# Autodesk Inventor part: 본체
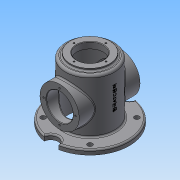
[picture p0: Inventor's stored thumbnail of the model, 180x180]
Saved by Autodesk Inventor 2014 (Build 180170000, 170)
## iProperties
Created: 2018-04
Part Number: 본체
Material: 일반
Document SubType Name: Modeling
Designer: NET
Density: 1 g/cm^3
Appearance: 기본값
Author: NET
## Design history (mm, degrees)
sketch "스케치1"
  geometry: L1 (0, 0)-(0, 133); L2 (0, 133)-(40, 133); L3 (40, 133)-(40, 128); L4 (40, 128)-(50, 128); L5 (50, 128)-(50, 0); L6 (50, 0)-(0, 0); L7 (27, 120)-(45, 120); L8 (45, 120)-(45, 0); L9 (0, 133)-(27, 133); L10 (27, 120)-(27, 133)
  constraints: 20 end point, 5 perpendicular, 2 parallel, 2 point on line, 1 vertical
  dimensions: "d0" = 133 distance of L1.start L1.end; "d1" = 80 diameter of L3 L1; "d2" = 100 diameter of L5 L1; "d4" = 5 distance of L2.end L3.end; "d12" = 90 diameter of L8 L1; "d14" = 13 distance of L7.start L9.end; "d15" = 54 diameter of L10 L1; "d16" = 120 distance of L7.end L8.end
revolve "회전1" stored, may be unused: angle "d5" = 90 deg
sketch "스케치2"
  geometry: L1 (-40, 133)-(40, 133) reference; L2 (-62, 68)-(62, 68); L3 (-50, 0)-(50, 0) reference; L4 (-62, 68)-(-62, 108); L5 (-62, 108)-(62, 108); L6 (62, 108)-(62, 68); 3 further points
  constraints: 8 end point, 2 midpoint, 2 parallel, 2 perpendicular, 1 vertical alignment
  dimensions: "d6" = 68 distance between parallel lines of L3 L2; "d7" = 124 distance of L2.start L2.end; "d8" = 80 diameter of L5 L2
revolve "회전2" sketch "스케치2" stored, may be unused: angle "d9" = 90 deg
fillet "모깎기1" dims "d10" = 5
revolve "회전3" stored, may be unused: angle "d17" = 90 deg
hole "구멍1" diameter "d20" = 54; stored, may be unused: countersink angle "d24" = 90 deg, drill point angle "d26" = 118 deg; dims "d18" = 10, "d19" = 10, "d21" = 6, "d22" = 4, "d23" = 2, "d25" = 8
sketch "스케치3" dims "d27" = 65
  geometry: C1 r 27 at (0, 0) reference; C2 r 40 at (0, 0) reference; 2 further points
  constraints: 2 vertical alignment, 1 coincident, 2 other
hole "구멍2" sketch "스케치3" at (0, 32.5) diameter "d28" = 3.242; stored, may be unused: countersink angle "d32" = 90 deg, drill point angle "d34" = 118 deg; dims "d29" = 8, "d30" = 4, "d31" = 2, "d33" = 10
sketch "스케치4" dims "d38" = 65
  geometry: C1 r 27 at (0, 0) reference; C2 r 40 at (0, 0) reference; 3 further points
  constraints: 2 vertical alignment, 1 coincident, 2 other
hole "구멍3" sketch "스케치4" at (0, 32.5) diameter "d39" = 3.242; stored, may be unused: countersink angle "d43" = 90 deg, drill point angle "d45" = 118 deg; dims "d40" = 8, "d41" = 4, "d42" = 2, "d44" = 10
chamfer "모따기1" distance "d49" = 1; stored, may be unused: second distance "d50" = 2, angle "d51" = 45 deg
fillet "모깎기2" dims "d52" = 3
fillet "모깎기3" dims "d53" = 3
fillet "모깎기4" dims "d54" = 3
chamfer "모따기2" distance "d55" = 1; stored, may be unused: second distance "d56" = 2, angle "d57" = 45 deg
node "작업 평면1"
sketch "스케치5"
  geometry: C1 r 15 at (0, -80); C2 r 15 at (0, 80); C3 r 45 at (0, 0); A1 r 80 centre (0, 0) between (0, -80) and (0, 80); 1 further point
  constraints: 4 centre point, 2 coincident, 2 point on circle, 2 vertical alignment
  dimensions: "d59" = 160 diameter of A1; "d61" = 30 diameter of C1; "d62" = 30 diameter of C2; "d79" = 90 diameter of C3
extrude "돌출1" join sketch "스케치5" distance "d63" = 10; taper "d64" = 0 deg
extrude "돌출2" cut sketch "스케치5" distance "d65" = 10; taper "d66" = 0 deg
extrude "돌출3" cut sketch "스케치5" distance "d67" = 10; taper "d68" = 0 deg
sketch "스케치6"
  geometry: L1 (0, 0)-(0, 67.5); L2 (0, 0)-(-47.73, 47.73); C1 r 50 at (0, 0) reference; A1 r 67.5 centre (0, 0) between (0, 67.5) and (-47.73, 47.73); 1 further point
  constraints: 4 end point, 2 coincident, 2 point on circle, 1 centre point, 1 vertical
  dimensions: "d69" = 135 diameter of A1; "d70" = 45 deg angle of L2 L1
hole "구멍4" sketch "스케치6" at (-47.73, 47.73) diameter "d71" = 10; stored, may be unused: countersink angle "d75" = 90 deg, drill point angle "d77" = 118 deg; dims "d72" = 8, "d73" = 4, "d74" = 2, "d76" = 10
fillet "모깎기5" dims "d78" = 3
extrude "돌출4" cut sketch "스케치5" distance "d80" = 10; taper "d81" = 0 deg
chamfer "모따기3" distance "d82" = 1; stored, may be unused: second distance "d83" = 2, angle "d84" = 45 deg
fillet "모깎기6" dims "d85" = 3
node "작업 평면3"
sketch "스케치8"
  geometry: L1 (-78.594, 15)-(78.594, 15) reference; L2 (-78.594, 15)-(78.594, 8) reference; L3 (78.594, 8)-(78.594, 8) reference; L4 (78.594, 8)-(78.594, 15) reference; L5 (78.594, 8)-(78.594, 8) reference; 6 further points
  constraints: 3 point on line, 1 coincident, 1 vertical alignment, 1 other
  dimensions: "d93" = 70 distance of point (0, 8) point (0, 78)
feature "엠보싱2" sketch "스케치8" dims "d94" = 0.5, "d95" = 0
node "솔리드1"
pattern_circular "원형 패턴1" dims angle "d36" = 360 deg
pattern_circular "원형 패턴2" dims angle "d47" = 360 deg
mirror "대칭1"
mirror "대칭2"
mirror "대칭3"
node "투영된 루프2"
other parameters: "d58" = 8, "d89" = 50.5
